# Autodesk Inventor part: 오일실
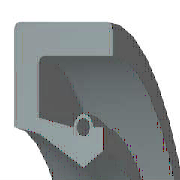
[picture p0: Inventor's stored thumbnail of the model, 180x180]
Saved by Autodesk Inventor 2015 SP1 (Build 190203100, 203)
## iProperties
Created: 2009-02
Part Number: 오일실
Material: 고무
Description: 오일-실
Document SubType Name: Modeling
Standard: KS B 2804
Designer: KYOUNG IL JANG
Standards Organization: KS
Language: ko-KR
Size Designation: S - 18 30 8
Categories: <MemberInstance><Categories><Category DisplayName="샤프트 부품" InternalName="7f7aeb1f-a693-4053-b835-cee3144e0d98" Mnemonic="SHFT"><Category DisplayName="실링" Intern
Density: 0.93 g/cm^3
Appearance: 고무(검은색)
Company: 한국ATC센터
IsCustomPart: 1
Author: KYOUNG IL JANG
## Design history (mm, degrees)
revolve "본체" stored, may be unused: angle "d17" = 90 deg
revolve "스프링1" stored, may be unused: angle "d18" = 90 deg
body "Solid1"
sketch "스케치1"
  geometry: L1 (0, 15)-(8, 15); L2 (8, 15)-(8, 13.75); L3 (8, 13.75)-(1.75, 13.75); L4 (0, 15)-(0, 11.1); L5 (0, 11.1)-(1.75, 10.75); L6 (1.75, 10.75)-(4.9, 9); L7 (4.9, 9)-(0, 9); L8 (6.3, 9.875)-(6.3, 11.1); L9 (0, 0)-(9.586, 0) reference; L10 (4.9, 9)-(6.3, 9.875); L11 (0, 18)-(0, -3) reference; L12 (-1.917, 0)-(11.503, 0) reference; L13 (4.2, 11.1)-(1.75, 11.59); L14 (1.75, 11.59)-(1.75, 13.75); L15 (6.3, 11.1)-(5.6, 11.1); C1 r 0.455 at (4.9, 11.1); A1 r 0.7 centre (4.9, 11.1) between (5.6, 11.1) and (4.2, 11.1)
  constraints: 26 end point, 5 horizontal alignment, 4 perpendicular, 2 centre point, 2 collinear, 2 horizontal, 2 parallel, 2 point on circle, 2 point on line, 2 vertical alignment, 1 coincident
  dimensions: "d0" = 30 diameter of L1 L9 (= SD2); "d1" = 19.75 diameter of L8.start L9 (= ABDM); "d2" = 1.25 distance of L1.end L2.end (computed from SD); "d3" = 0.91 diameter of C1 (= SPDI); "d4" = 1.4 diameter of A1 (= SPDA); "d5" = 18 diameter of L6.end L9 (= NND); "d6" = 21.5 diameter of L5.end L9 (= TKDM); "d7" = 22.2 diameter of L4.end L9 (= HLDM); "d8" = 4.9 distance from line of C1.centre L4 (= SPDST); "d9" = 6.3 distance between parallel lines of L8 L4 (= SDI); "d10" = 8 distance between parallel lines of L2 L4 (= SWDT); "d12" = 1.75 distance between parallel lines of L14 L4 (= SD)
fillet "모깎기1" dims "d11" = 0.3 (= RR)
other parameters: "SD2" = 30 [user parameter; used in 1 equation term], "SWDT" = 8 [user parameter; used in 1 equation term], "RR" = 0.3 [user parameter; used in 1 equation term], "SD" = 1.75 [user parameter; used in 2 equation terms], "NND" = 18 [user parameter; used in 1 equation term], "SPDA" = 1.4 [user parameter; used in 1 equation term], "SPDI" = 0.91 [user parameter; used in 1 equation term], "TKDM" = 21.5 [user parameter; used in 1 equation term], "HLDM" = 22.2 [user parameter; used in 1 equation term], "ABDM" = 19.75 [user parameter; used in 1 equation term], "SDI" = 6.3 [user parameter; used in 1 equation term], "SPDST" = 4.9 [user parameter; used in 1 equation term], "d13" = 0, "d14" = 0, "d15" = 0, "LAB" = 0.35 [user parameter]
